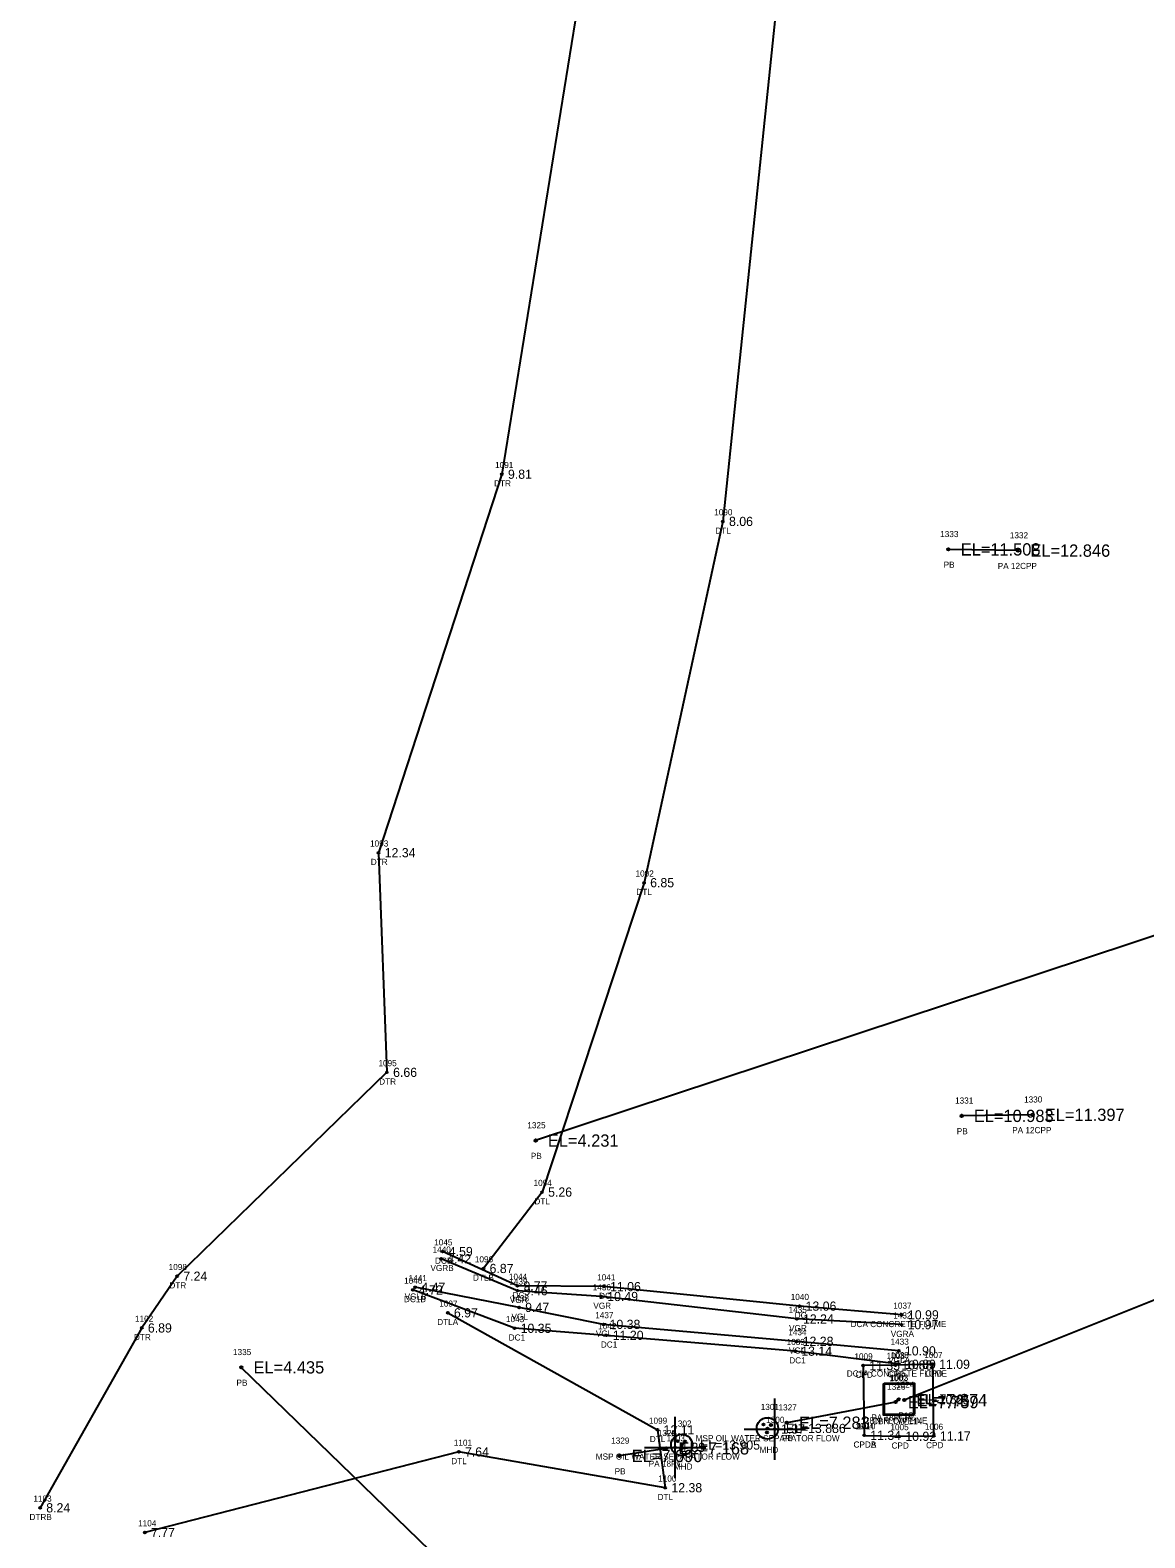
# Model space of a CAD drawing. Extents: x 2072307 to 2072993, y 127574 to 129736.
# Drawn here: x 2072306.6 to 2072488.4, y 128070.8 to 128316.6 of the extents above; entities that cross this region are included whole.
import ezdxf

# ---------------------------------------------------------------- set-up
doc = ezdxf.new("R2010")
doc.units = 0
for name, color, linetype in [('RD_EX_Conc', 7, 'Continuous'), ('RD_EX_Conc_txCode', 7, 'Continuous'), ('RD_EX_DR_Inlet', 7, 'Continuous'), ('RD_EX_DR_Inlet_txCode', 7, 'Continuous'), ('RD_EX_DR_Pipe', 7, 'Continuous'), ('RD_EX_DR_Pipe_txCode', 7, 'Continuous'), ('RD_EX_H2O', 7, 'Continuous'), ('RD_EX_H2O_txCode', 7, 'Continuous'), ('RD_EX_Misc', 7, 'Continuous'), ('RD_EX_Misc_txCode', 7, 'Continuous'), ('RD_EX_Road', 7, 'Continuous'), ('RD_EX_Road_txCode', 7, 'Continuous'), ('RD_EX_TX_Conc_ELEV', 7, 'Continuous'), ('RD_EX_TX_DR_Inlet_ELEV', 7, 'Continuous'), ('RD_EX_TX_H2O_ELEV', 7, 'Continuous'), ('RD_EX_TX_Misc_ELEV', 7, 'Continuous'), ('RD_EX_TX_Road_ELEV', 7, 'Continuous'), ('RD_SMD_Locator', 7, 'Continuous'), ('RD_TX_Pipe_ElevEX', 7, 'Continuous')]:
    doc.layers.add(name, color=color, linetype=linetype)

msp = doc.modelspace()

# ---------------------------------------------------------------- linework, layer by layer
at = {"layer": 'RD_EX_Conc'}
for points in [[(2072448.74, 128107.16), (2072432.05, 128108.58), (2072400.16, 128111.76), (2072386.04, 128111.87), (2072373.86, 128117.48)], [(2072448.27, 128099.1), (2072431.34, 128101.24), (2072400.6, 128103.82), (2072385.58, 128104.97), (2072368.98, 128111.22)], [(2072442.59, 128087.52), (2072448.31, 128087.36), (2072453.95, 128087.42), (2072453.82, 128099.11), (2072447.69, 128098.97), (2072442.43, 128098.89), (2072442.59, 128087.52)]]:
    msp.add_lwpolyline(points, dxfattribs=at)
at = {"layer": 'RD_EX_DR_Inlet'}
for p, q in [((2072450.72, 128090.88), (2072450.72, 128095.88)), ((2072450.84, 128090.97), (2072450.84, 128095.97))]:
    msp.add_line(p, q, dxfattribs=at)
for points in [[(2072450.72, 128090.88), (2072450.72, 128095.88), (2072445.72, 128095.88), (2072445.72, 128090.88)], [(2072450.84, 128090.97), (2072450.84, 128095.97), (2072445.84, 128095.97), (2072445.84, 128090.97)]]:
    msp.add_lwpolyline(points, close=True, dxfattribs=at)
for centre, radius in [((2072426.83, 128088.65), 1.75), ((2072426.17, 128089.28), 0.175), ((2072427.39, 128089.21), 0.175), ((2072412.85, 128085.94), 1.75), ((2072412.19, 128086.57), 0.175), ((2072413.41, 128086.5), 0.175), ((2072426.74, 128087.98), 0.175), ((2072412.77, 128085.28), 0.175)]:
    msp.add_circle(centre, radius, dxfattribs=at)
at = {"layer": 'RD_EX_DR_Pipe'}
for p, q in [((2072708.36, 128241.23), (2072389.02, 128135.57)), ((2072467.7, 128231.73), (2072456.34, 128231.93)), ((2072675.58, 128183.7), (2072449.14, 128093.27)), ((2072470.06, 128139.77), (2072458.48, 128139.59)), ((2072414.52, 128027.27), (2072341.02, 128098.6)), ((2072447.72, 128092.94), (2072429.98, 128089.58)), ((2072410.3, 128085.4), (2072402.69, 128084.16))]:
    msp.add_line(p, q, dxfattribs=at)
at = {"layer": 'RD_EX_H2O'}
for points in [[(2072403.62, 128560.29), (2072411.45, 128462.26), (2072432.66, 128362.62), (2072419.56, 128236.49), (2072406.7, 128177.6), (2072390.06, 128127.17), (2072380.51, 128114.72)], [(2072394.05, 128557.65), (2072400.51, 128459.22), (2072402.07, 128358.79), (2072383.51, 128244.18), (2072363.41, 128182.49), (2072364.78, 128146.69), (2072330.57, 128113.46), (2072324.79, 128105.03), (2072308.22, 128075.71)], [(2072374.7, 128107.49), (2072408.89, 128088.41), (2072410.16, 128078.98), (2072376.5, 128084.82), (2072325.3, 128071.69)]]:
    msp.add_lwpolyline(points, dxfattribs=at)
at = {"layer": 'RD_EX_Misc'}
for p, q in [((2072428.04, 128083.55), (2072428.04, 128093.55)), ((2072411.76, 128080.56), (2072411.76, 128090.56)), ((2072423.04, 128088.55), (2072433.04, 128088.55)), ((2072406.76, 128085.56), (2072416.76, 128085.56))]:
    msp.add_line(p, q, dxfattribs=at)
at = {"layer": 'RD_EX_Road'}
for points in [[(2072448.68, 128105.56), (2072431.62, 128106.49), (2072399.7, 128110.15), (2072386.07, 128111.1), (2072373.61, 128116.3)], [(2072448.25, 128101.29), (2072431.57, 128102.84), (2072400.08, 128105.61), (2072386.32, 128108.37), (2072369.39, 128111.65)]]:
    msp.add_lwpolyline(points, dxfattribs=at)
at = {"layer": 'RD_SMD_Locator'}
for centre, radius in [((2072383.51, 128244.18), 0.15), ((2072419.56, 128236.49), 0.15), ((2072456.34, 128231.93), 0.2), ((2072467.7, 128231.73), 0.2), ((2072363.41, 128182.49), 0.15), ((2072406.7, 128177.6), 0.15), ((2072364.78, 128146.69), 0.15), ((2072458.48, 128139.59), 0.2), ((2072470.06, 128139.77), 0.2), ((2072389.02, 128135.57), 0.2), ((2072390.06, 128127.17), 0.15), ((2072373.61, 128116.3), 0.15), ((2072373.86, 128117.48), 0.15), ((2072380.51, 128114.72), 0.15), ((2072330.57, 128113.46), 0.15), ((2072368.98, 128111.22), 0.15), ((2072369.39, 128111.65), 0.15), ((2072386.04, 128111.87), 0.15), ((2072386.07, 128111.1), 0.15), ((2072400.16, 128111.76), 0.15), ((2072399.7, 128110.15), 0.15), ((2072374.7, 128107.49), 0.15), ((2072386.32, 128108.37), 0.15), ((2072431.62, 128106.49), 0.15), ((2072432.05, 128108.58), 0.15), ((2072448.74, 128107.16), 0.15), ((2072324.79, 128105.03), 0.15), ((2072385.58, 128104.97), 0.15), ((2072400.08, 128105.61), 0.15), ((2072400.6, 128103.82), 0.15), ((2072448.68, 128105.56), 0.15), ((2072431.34, 128101.24), 0.15), ((2072431.57, 128102.84), 0.15), ((2072448.25, 128101.29), 0.15), ((2072442.43, 128098.89), 0.15), ((2072447.69, 128098.97), 0.15), ((2072448.27, 128099.1), 0.15), ((2072453.82, 128099.11), 0.15), ((2072341.02, 128098.6), 0.2), ((2072447.72, 128092.94), 0.2), ((2072448.13, 128093.33), 0.15), ((2072448.25, 128093.43), 0.15), ((2072449.14, 128093.27), 0.2), ((2072429.98, 128089.58), 0.2), ((2072408.89, 128088.41), 0.15), ((2072426.83, 128088.65), 0.15), ((2072428.04, 128088.55), 0.15), ((2072442.59, 128087.52), 0.15), ((2072442.59, 128087.52), 0.15), ((2072448.31, 128087.36), 0.15), ((2072453.95, 128087.42), 0.15), ((2072376.5, 128084.82), 0.15), ((2072402.69, 128084.16), 0.2), ((2072410.3, 128085.4), 0.2), ((2072411.76, 128085.56), 0.15), ((2072412.85, 128085.94), 0.15), ((2072410.16, 128078.98), 0.15), ((2072308.22, 128075.71), 0.15), ((2072325.3, 128071.69), 0.15)]:
    msp.add_circle(centre, radius, dxfattribs=at)

# ---------------------------------------------------------------- texts
at = {"layer": 'RD_EX_Conc_txCode'}
for s, p in [('1045', (2072372.48, 128118.48)), ('DCB', (2072372.61, 128115.48)), ('1044', (2072384.66, 128112.87)), ('1041', (2072399.05, 128112.76)), ('1046', (2072367.57, 128112.22)), ('DC1B', (2072367.56, 128109.22)), ('DC', (2072385.26, 128109.87)), ('DC', (2072399.38, 128109.76)), ('1040', (2072430.62, 128109.58)), ('1037', (2072447.35, 128108.16)), ('1043', (2072384.19, 128105.97)), ('DC', (2072431.27, 128106.58)), ('DC1', (2072384.63, 128102.97)), ('1042', (2072399.22, 128104.82)), ('DCA CONCRETE FLUME', (2072440.39, 128105.16)), ('DC1', (2072399.66, 128101.82)), ('1039', (2072429.95, 128102.24)), ('DC1', (2072430.39, 128099.24)), ('1009', (2072441.01, 128099.89)), ('1008', (2072446.26, 128099.97)), ('1038', (2072446.89, 128100.1)), ('1007', (2072452.4, 128100.11)), ('DC1A CONCRETE FLUME', (2072439.76, 128097.1)), ('CPD', (2072441.18, 128096.89)), ('CPD', (2072446.44, 128096.97)), ('CPD', (2072452.57, 128097.11)), ('1004', (2072441.16, 128088.52)), ('1010', (2072441.45, 128088.52)), ('1005', (2072446.88, 128088.36)), ('1006', (2072452.5, 128088.42)), ('CPDA', (2072440.85, 128085.52)), ('CPDB', (2072440.87, 128085.52)), ('CPD', (2072447.06, 128085.36)), ('CPD', (2072452.7, 128085.42))]:
    msp.add_text(s, height=1, dxfattribs=at).set_placement(p)
at = {"layer": 'RD_EX_DR_Inlet_txCode'}
for s, p in [('1002', (2072446.7, 128096.33)), ('1003', (2072446.82, 128096.43)), ('1301', (2072425.73, 128091.65)), ('1302', (2072411.47, 128088.94)), ('CBN FLOW LINE', (2072442.51, 128089.43)), ('CBN TYPE14', (2072443.9, 128089.33)), ('MHD', (2072425.54, 128084.65)), ('MHD', (2072411.56, 128081.94))]:
    msp.add_text(s, height=1, dxfattribs=at).set_placement(p)
at = {"layer": 'RD_EX_DR_Pipe_txCode'}
for s, p in [('1333', (2072454.99, 128233.93)), ('1332', (2072466.35, 128233.73)), ('PB', (2072455.56, 128228.93)), ('PA 12CPP', (2072464.38, 128228.73)), ('1331', (2072457.42, 128141.59)), ('1330', (2072468.67, 128141.77)), ('1325', (2072387.67, 128137.57)), ('PB', (2072457.7, 128136.59)), ('PA 12CPP', (2072466.74, 128136.77)), ('PB', (2072388.24, 128132.57)), ('1335', (2072339.67, 128100.6)), ('PB', (2072340.24, 128095.6)), ('1326', (2072446.35, 128094.94)), ('1324', (2072447.79, 128095.27)), ('1327', (2072428.63, 128091.58)), ('PA 18IN RC', (2072443.77, 128089.94)), ('P1B', (2072448.19, 128090.27)), ('1329', (2072401.34, 128086.16)), ('1328', (2072408.95, 128087.4)), ('PB', (2072429.2, 128086.58)), ('PB', (2072401.91, 128081.16)), ('PA 18RC', (2072407.46, 128082.4))]:
    msp.add_text(s, height=1, dxfattribs=at).set_placement(p)
at = {"layer": 'RD_EX_H2O_txCode'}
for s, p in [('1091', (2072382.41, 128245.18)), ('DTR', (2072382.25, 128242.18)), ('1090', (2072418.14, 128237.49)), ('DTL', (2072418.32, 128234.49)), ('1093', (2072362.02, 128183.49)), ('DTR', (2072362.14, 128180.49)), ('1092', (2072405.31, 128178.6)), ('DTL', (2072405.45, 128175.6)), ('1095', (2072363.39, 128147.69)), ('DTR', (2072363.51, 128144.69)), ('1094', (2072388.68, 128128.17)), ('DTL', (2072388.82, 128125.17)), ('1096', (2072379.11, 128115.72)), ('1098', (2072329.18, 128114.46)), ('DTLB', (2072378.8, 128112.72)), ('DTR', (2072329.3, 128111.46)), ('1097', (2072373.31, 128108.49)), ('1102', (2072323.69, 128106.03)), ('DTLA', (2072372.97, 128105.49)), ('DTR', (2072323.52, 128103.03)), ('1099', (2072407.5, 128089.41)), ('1101', (2072375.68, 128085.82)), ('DTL', (2072407.64, 128086.41)), ('DTL', (2072375.26, 128082.82)), ('1100', (2072409.01, 128079.98)), ('1103', (2072307.12, 128076.71)), ('DTL', (2072408.91, 128076.98)), ('DTRB', (2072306.48, 128073.71)), ('1104', (2072324.2, 128072.69))]:
    msp.add_text(s, height=1, dxfattribs=at).set_placement(p)
at = {"layer": 'RD_EX_Misc_txCode'}
for s, p in [('1300', (2072426.62, 128089.55)), ('1303', (2072410.37, 128086.56)), ('MSP OIL WATER SEPARATOR FLOW', (2072415.11, 128086.55)), ('MSP OIL WATER SEPARATOR FLOW', (2072398.83, 128083.56))]:
    msp.add_text(s, height=1, dxfattribs=at).set_placement(p)
at = {"layer": 'RD_EX_Road_txCode'}
for s, p in [('1440', (2072372.22, 128117.3)), ('VGRB', (2072371.87, 128114.3)), ('1441', (2072368.32, 128112.65)), ('1439', (2072384.73, 128112.1)), ('1436', (2072398.33, 128111.15)), ('VGLB', (2072367.67, 128109.65)), ('VGR', (2072384.81, 128109.1)), ('1438', (2072384.97, 128109.37)), ('VGR', (2072398.43, 128108.15)), ('VGL', (2072385.08, 128106.37)), ('1437', (2072398.74, 128106.61)), ('1435', (2072430.27, 128107.49)), ('1432', (2072447.34, 128106.56)), ('VGL', (2072398.84, 128103.61)), ('1434', (2072430.22, 128103.84)), ('VGR', (2072430.35, 128104.49)), ('VGRA', (2072446.93, 128103.56)), ('VGL', (2072430.32, 128100.84)), ('1433', (2072446.9, 128102.29)), ('VGLA', (2072446.52, 128099.29))]:
    msp.add_text(s, height=1, dxfattribs=at).set_placement(p)
at = {"layer": 'RD_EX_TX_Conc_ELEV'}
for s, p in [('4.59', (2072374.86, 128116.73)), ('4.72', (2072369.98, 128110.47)), ('9.77', (2072387.04, 128111.12)), ('11.06', (2072401.16, 128111.01)), ('13.06', (2072433.05, 128107.83)), ('10.99', (2072449.74, 128106.41)), ('10.35', (2072386.58, 128104.22)), ('11.20', (2072401.6, 128103.07)), ('13.14', (2072432.34, 128100.49)), ('11.35', (2072443.43, 128098.14)), ('10.88', (2072448.69, 128098.22)), ('10.89', (2072449.27, 128098.35)), ('11.09', (2072454.82, 128098.36)), ('11.34', (2072443.59, 128086.77)), ('11.34', (2072443.59, 128086.77)), ('10.92', (2072449.31, 128086.61)), ('11.17', (2072454.95, 128086.67))]:
    msp.add_text(s, height=1.5, dxfattribs=at).set_placement(p)
at = {"layer": 'RD_EX_TX_DR_Inlet_ELEV'}
for s, p in [('EL=10.65', (2072451.13, 128092.58)), ('EL=7.82', (2072451.25, 128092.68)), ('EL=13.886', (2072429.83, 128087.9)), ('EL=13.905', (2072415.85, 128085.19))]:
    msp.add_text(s, height=1.5, dxfattribs=at).set_placement(p)
at = {"layer": 'RD_EX_TX_H2O_ELEV'}
for s, p in [('9.81', (2072384.51, 128243.43)), ('8.06', (2072420.56, 128235.74)), ('12.34', (2072364.41, 128181.74)), ('6.85', (2072407.7, 128176.85)), ('6.66', (2072365.78, 128145.94)), ('5.26', (2072391.06, 128126.42)), ('7.24', (2072331.57, 128112.71)), ('6.87', (2072381.51, 128113.97)), ('6.97', (2072375.7, 128106.74)), ('6.89', (2072325.79, 128104.28)), ('12.11', (2072409.89, 128087.66)), ('7.64', (2072377.5, 128084.07)), ('12.38', (2072411.16, 128078.23)), ('8.24', (2072309.22, 128074.96)), ('7.77', (2072326.3, 128070.94))]:
    msp.add_text(s, height=1.5, dxfattribs=at).set_placement(p)
at = {"layer": 'RD_EX_TX_Misc_ELEV'}
for s, p in [('1.37', (2072429.04, 128087.8)), ('1.39', (2072412.76, 128084.81))]:
    msp.add_text(s, height=1.5, dxfattribs=at).set_placement(p)
at = {"layer": 'RD_EX_TX_Road_ELEV'}
for s, p in [('4.42', (2072374.61, 128115.55)), ('4.47', (2072370.39, 128110.9)), ('9.46', (2072387.07, 128110.35)), ('9.47', (2072387.32, 128107.62)), ('10.49', (2072400.7, 128109.4)), ('10.38', (2072401.08, 128104.86)), ('12.24', (2072432.62, 128105.74)), ('10.97', (2072449.68, 128104.81)), ('12.28', (2072432.57, 128102.09)), ('10.90', (2072449.25, 128100.54))]:
    msp.add_text(s, height=1.5, dxfattribs=at).set_placement(p)
at = {"layer": 'RD_TX_Pipe_ElevEX'}
for s, p in [('EL=11.508', (2072458.34, 128230.93)), ('EL=12.846', (2072469.7, 128230.73)), ('EL=11.397', (2072472.06, 128138.77)), ('EL=10.983', (2072460.48, 128138.59)), ('EL=4.231', (2072391.02, 128134.57)), ('EL=4.435', (2072343.02, 128097.6)), ('EL=7.874', (2072451.14, 128092.27)), ('EL=7.759', (2072449.72, 128091.94)), ('EL=7.283', (2072431.98, 128088.58)), ('EL=7.090', (2072404.69, 128083.16)), ('EL=7.168', (2072412.3, 128084.4))]:
    msp.add_text(s, height=2, dxfattribs=at).set_placement(p)

doc.saveas('drawing.dxf')
